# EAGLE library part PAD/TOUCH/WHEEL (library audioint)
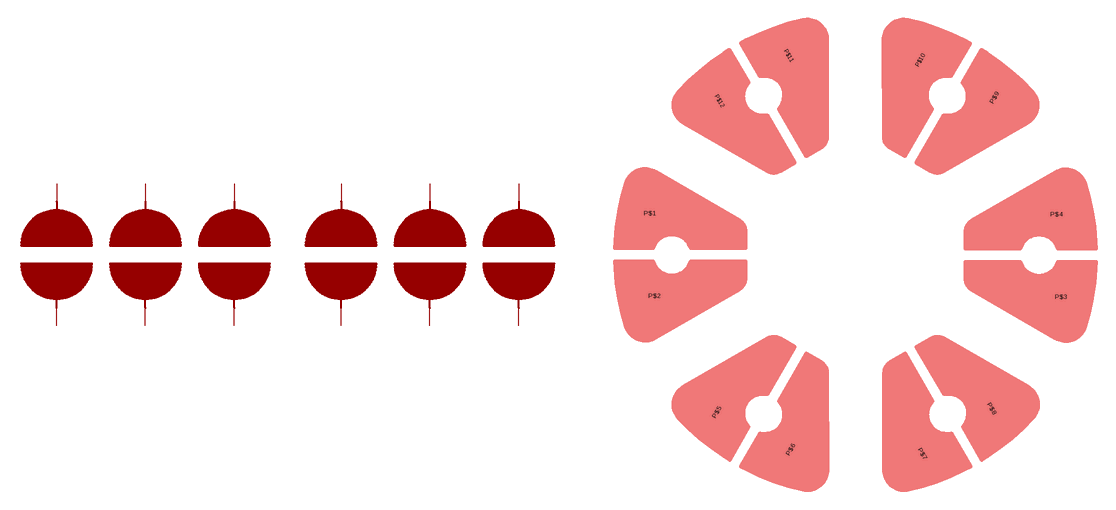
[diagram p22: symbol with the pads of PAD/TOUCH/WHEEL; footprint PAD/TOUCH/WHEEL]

Designator prefix -; gates G$1=PAD/TOUCH G$2=PAD/TOUCH G$3=PAD/TOUCH G$4=PAD/TOUCH G$5=PAD/TOUCH G$6=PAD/TOUCH

## PAD/TOUCH/WHEEL  [PAD/TOUCH/WHEEL]
P$1  G$1:P$1
P$2  G$1:P$2
P$3  G$2:P$1
P$4  G$2:P$2
P$5  G$3:P$1
P$6  G$3:P$2
P$7  G$4:P$1
P$8  G$4:P$2
P$9  G$5:P$1
P$10  G$5:P$2
P$11  G$6:P$1
P$12  G$6:P$2

## Footprint PAD/TOUCH/WHEEL (pad centres in mm)
smd 1.016 x 0.508: P$1 -15.926,3.226; P$2 -15.57,-3.175; P$3 15.926,-3.251; P$4 15.57,3.15
smd 1.016 x 0.508 rotated 60: P$5 -10.753,-12.187; P$6 -5.032,-15.079
smd 1.016 x 0.508 rotated 120: P$7 5.198,-15.413; P$8 10.564,-11.904
smd 1.016 x 0.508 rotated 240: P$9 10.753,12.187; P$10 5.032,15.079
smd 1.016 x 0.508 rotated 300: P$11 -5.173,15.413; P$12 -10.538,11.904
